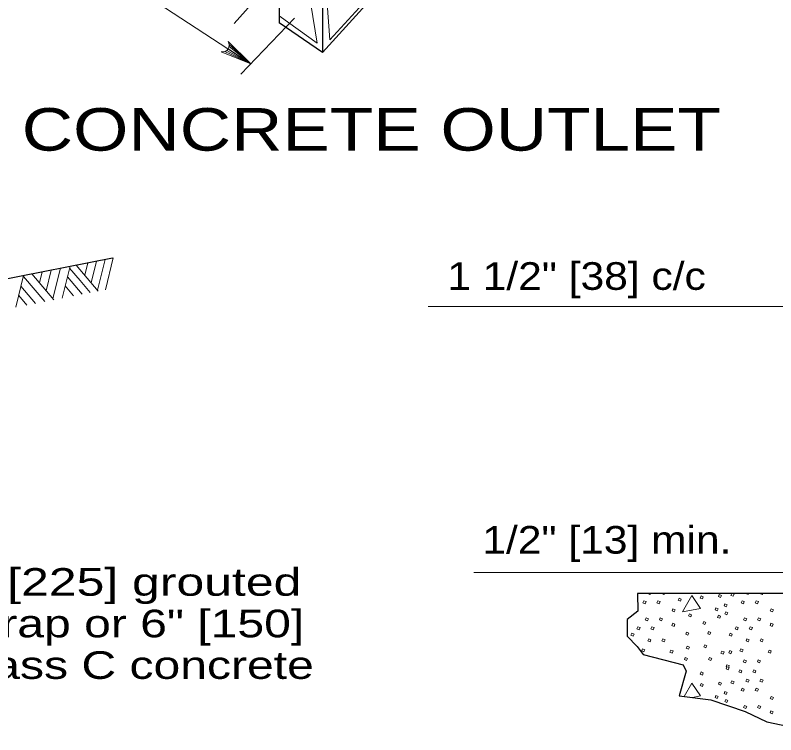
# Model space of a CAD drawing. Extents: x 1083.1 to 1117.1, y 697.4 to 741.4.
# Drawn here: x 1097.384 to 1101.675, y 729.151 to 733.213 of the extents above; entities that cross this region are included whole.
import ezdxf

# ---------------------------------------------------------------- set-up
doc = ezdxf.new("R2010")
doc.units = 0
doc.header["$LTSCALE"] = 0.062
doc.layers.add('1', color=7, linetype='Continuous', lineweight=13)

msp = doc.modelspace()

# ---------------------------------------------------------------- linework, layer by layer
at = {"layer": '1'}
for p, q in [((1098.61942, 733.16592), (1099.34742, 733.98267)), ((1098.71317, 732.93875), (1097.63775, 733.64192)), ((1098.96042, 733.19633), (1098.65742, 732.88083)), ((1098.591, 733.04817), (1098.71317, 732.93875)), ((1098.56675, 733.00767), (1098.71317, 732.93875)), ((1098.57733, 733.01392), (1098.71317, 732.93875)), ((1098.58492, 733.0225), (1098.71317, 732.93875)), ((1098.5905, 733.03617), (1098.71317, 732.93875)), ((1097.93658, 731.84333), (1097.8925, 731.66317)), ((1097.72817, 731.80233), (1097.85183, 731.65558)), ((1097.794, 731.81525), (1097.77708, 731.7445)), ((1097.84192, 731.82475), (1097.81267, 731.70267)), ((1097.8915, 731.8345), (1097.84883, 731.66042)), ((1097.53617, 731.7645), (1097.52108, 731.70267)), ((1097.58742, 731.77458), (1097.55858, 731.65792)), ((1097.63925, 731.78475), (1097.5965, 731.61333)), ((1097.69325, 731.7955), (1097.649, 731.61575)), ((1097.69067, 731.78433), (1097.74933, 731.71517)), ((1097.43083, 731.74383), (1097.3865, 731.564)), ((1097.42975, 731.73883), (1097.54983, 731.59625)), ((1097.47808, 731.75308), (1097.60225, 731.6065)), ((1097.67867, 731.73633), (1097.76225, 731.638)), ((1097.74933, 731.71517), (1097.80675, 731.64683)), ((1097.41608, 731.68308), (1097.4975, 731.58592)), ((1097.666, 731.68442), (1097.71267, 731.62825)), ((1097.404, 731.63067), (1097.44908, 731.57633)), ((1102.63992, 731.56783), (1099.71408, 731.56783)), ((1099.97208, 730.06625), (1103.79292, 730.06625)), ((1101.39442, 729.53533), (1101.39942, 729.54675)), ((1101.20075, 729.44292), (1101.158, 729.36708))]:
    msp.add_line(p, q, dxfattribs=at)
at = {"layer": '1', "lineweight": 25}
for p, q in [((1099.11717, 733.00283), (1099.59808, 733.531)), ((1098.87317, 733.45058), (1098.87317, 733.16992)), ((1099.11717, 733.2835), (1099.11717, 733.00283)), ((1099.11717, 733.00283), (1098.87317, 733.16992)), ((1096.21767, 731.505), (1097.9335, 731.84267)), ((1100.89692, 729.84967), (1100.83692, 729.80233))]:
    msp.add_line(p, q, dxfattribs=at)
at = {"layer": '1'}
for points in [[(1098.87317, 733.3975), (1098.87492, 733.39883), (1099.05217, 733.275), (1099.08667, 733.05583), (1098.87317, 733.2095)], [(1098.58442, 733.06525), (1098.71317, 732.93875), (1098.54567, 733.00592)], [(1100.96775, 729.94858), (1100.96508, 729.9425), (1100.95258, 729.94792), (1100.95292, 729.94858)], [(1101.04692, 729.94858), (1101.04433, 729.9425), (1101.03183, 729.94792), (1101.03208, 729.94858)], [(1101.42992, 729.94858), (1101.43958, 729.94442), (1101.43442, 729.93258), (1101.42192, 729.938), (1101.42658, 729.94858)], [(1101.52208, 729.94858), (1101.51942, 729.9425), (1101.50692, 729.94792), (1101.50725, 729.94858)], [(1101.60125, 729.94858), (1101.59858, 729.9425), (1101.58608, 729.94792), (1101.58642, 729.94858)], [(1101.39942, 729.54675), (1101.41192, 729.54133), (1101.40933, 729.53533)], [(1101.20508, 729.36133), (1101.25075, 729.37025), (1101.20075, 729.44292)]]:
    msp.add_lwpolyline(points, dxfattribs=at)
for points in [[(1099.15817, 733.07442), (1099.14325, 733.2795), (1099.26625, 733.41375), (1099.40783, 733.34658)], [(1101.12942, 729.92267), (1101.14192, 729.91725), (1101.13675, 729.90542), (1101.12425, 729.91083)], [(1101.20075, 729.93733), (1101.1485, 729.84475), (1101.25075, 729.86475)], [(1101.25358, 729.93492), (1101.26608, 729.9295), (1101.26092, 729.91767), (1101.24842, 729.92308)], [(1101.35633, 729.94275), (1101.36883, 729.93733), (1101.36367, 729.9255), (1101.35117, 729.93092)], [(1100.93083, 729.908), (1100.94333, 729.90258), (1100.93817, 729.89083), (1100.92567, 729.89625)], [(1101.01008, 729.908), (1101.02258, 729.90258), (1101.01742, 729.89083), (1101.00492, 729.89625)], [(1101.38817, 729.89042), (1101.40058, 729.885), (1101.3955, 729.87317), (1101.383, 729.87858)], [(1101.48517, 729.908), (1101.49767, 729.90258), (1101.4925, 729.89083), (1101.48, 729.89625)], [(1101.56442, 729.908), (1101.57683, 729.90258), (1101.57175, 729.89083), (1101.55925, 729.89625)], [(1101.095, 729.86208), (1101.1075, 729.85667), (1101.10233, 729.84483), (1101.08983, 729.85025)], [(1101.18775, 729.83417), (1101.20025, 729.82875), (1101.19508, 729.81692), (1101.18258, 729.82233)], [(1101.33783, 729.86775), (1101.35033, 729.86233), (1101.34517, 729.8505), (1101.33267, 729.85592)], [(1101.39242, 729.84483), (1101.40483, 729.83942), (1101.39975, 729.82758), (1101.38725, 729.833)], [(1101.64933, 729.86208), (1101.66183, 729.85667), (1101.65667, 729.84483), (1101.64417, 729.85025)], [(1100.94425, 729.81083), (1100.95675, 729.80542), (1100.95158, 729.79358), (1100.93908, 729.799)], [(1101.0235, 729.81083), (1101.036, 729.80542), (1101.03083, 729.79358), (1101.01833, 729.799)], [(1101.26842, 729.791), (1101.28092, 729.78558), (1101.27575, 729.77375), (1101.26325, 729.77917)], [(1101.35133, 729.82567), (1101.36383, 729.82025), (1101.35867, 729.80842), (1101.34617, 729.81383)], [(1101.49858, 729.81083), (1101.51108, 729.80542), (1101.50592, 729.79358), (1101.49342, 729.799)], [(1101.57775, 729.81083), (1101.59025, 729.80542), (1101.58508, 729.79358), (1101.57258, 729.799)], [(1100.89683, 729.76125), (1100.90933, 729.75583), (1100.90417, 729.74408), (1100.89167, 729.7495)], [(1100.97608, 729.76125), (1100.98858, 729.75583), (1100.98342, 729.74408), (1100.97092, 729.7495)], [(1101.09358, 729.78033), (1101.10608, 729.77492), (1101.10092, 729.76308), (1101.08842, 729.7685)], [(1101.45117, 729.76125), (1101.46367, 729.75583), (1101.4585, 729.74408), (1101.446, 729.7495)], [(1101.53042, 729.76125), (1101.54292, 729.75583), (1101.53775, 729.74408), (1101.52525, 729.7495)], [(1101.64792, 729.78033), (1101.66042, 729.77492), (1101.65525, 729.76308), (1101.64275, 729.7685)], [(1100.86292, 729.72517), (1100.87533, 729.71975), (1100.87017, 729.70792), (1100.85775, 729.71333)], [(1101.17217, 729.73017), (1101.18467, 729.72475), (1101.1795, 729.71292), (1101.167, 729.71833)], [(1101.29608, 729.73367), (1101.30858, 729.72825), (1101.30342, 729.71642), (1101.29092, 729.72183)], [(1101.41717, 729.72517), (1101.42967, 729.71975), (1101.4245, 729.70792), (1101.412, 729.71333)], [(1100.95842, 729.69258), (1100.97092, 729.68717), (1100.96575, 729.67533), (1100.95325, 729.68075)], [(1101.03767, 729.69258), (1101.05008, 729.68717), (1101.04492, 729.67533), (1101.0325, 729.68075)], [(1101.27408, 729.65933), (1101.28658, 729.65392), (1101.28142, 729.64208), (1101.26892, 729.6475)], [(1101.51275, 729.69258), (1101.52525, 729.68717), (1101.52008, 729.67533), (1101.50758, 729.68075)], [(1101.59192, 729.69258), (1101.60442, 729.68717), (1101.59925, 729.67533), (1101.58675, 729.68075)], [(1100.92375, 729.63667), (1100.93625, 729.63125), (1100.93108, 729.61942), (1100.91858, 729.62483)], [(1101.08292, 729.62958), (1101.09542, 729.62417), (1101.09025, 729.61242), (1101.07775, 729.61775)], [(1101.17508, 729.651), (1101.18758, 729.64558), (1101.18242, 729.63375), (1101.16992, 729.63917)], [(1101.3705, 729.62392), (1101.383, 729.6185), (1101.37783, 729.60675), (1101.36533, 729.61208)], [(1101.415, 729.626), (1101.4275, 729.62058), (1101.42233, 729.60883), (1101.40983, 729.61417)], [(1101.47808, 729.63667), (1101.49058, 729.63125), (1101.48542, 729.61942), (1101.47292, 729.62483)], [(1101.63725, 729.62958), (1101.64975, 729.62417), (1101.64458, 729.61242), (1101.63208, 729.61775)], [(1101.16467, 729.58692), (1101.17717, 729.5815), (1101.172, 729.56967), (1101.1595, 729.57508)], [(1101.301, 729.58717), (1101.3135, 729.58175), (1101.30833, 729.56992), (1101.29583, 729.57533)], [(1101.49717, 729.57442), (1101.50967, 729.569), (1101.5045, 729.55717), (1101.492, 729.56258)], [(1101.57633, 729.57442), (1101.58883, 729.569), (1101.58367, 729.55717), (1101.57117, 729.56258)], [(1101.39942, 729.53533), (1101.41192, 729.52992), (1101.40675, 729.51808), (1101.39433, 729.5235)], [(1101.25358, 729.50558), (1101.26608, 729.50017), (1101.26092, 729.48833), (1101.24842, 729.49375)], [(1101.47167, 729.51833), (1101.48417, 729.51292), (1101.479, 729.50108), (1101.4665, 729.5065)], [(1101.55092, 729.51833), (1101.56342, 729.51292), (1101.55825, 729.50108), (1101.54575, 729.5065)], [(1101.25358, 729.4405), (1101.26608, 729.43508), (1101.26092, 729.42325), (1101.24842, 729.42867)], [(1101.35633, 729.44833), (1101.36883, 729.44292), (1101.36367, 729.43108), (1101.35117, 729.4365)], [(1101.42708, 729.45542), (1101.43958, 729.45), (1101.43442, 729.43817), (1101.42192, 729.44358)], [(1101.51208, 729.46533), (1101.52458, 729.45992), (1101.51942, 729.44808), (1101.50692, 729.4535)], [(1101.59125, 729.46533), (1101.60375, 729.45992), (1101.59858, 729.44808), (1101.58608, 729.4535)], [(1101.48517, 729.41358), (1101.49767, 729.40817), (1101.4925, 729.39633), (1101.48, 729.40175)], [(1101.56442, 729.41358), (1101.57683, 729.40817), (1101.57175, 729.39633), (1101.55925, 729.40175)], [(1101.33783, 729.37325), (1101.35033, 729.36783), (1101.34517, 729.356), (1101.33267, 729.36142)], [(1101.38817, 729.39592), (1101.40058, 729.3905), (1101.3955, 729.37867), (1101.383, 729.38408)], [(1101.64933, 729.36758), (1101.66183, 729.36217), (1101.65667, 729.35033), (1101.64417, 729.35575)], [(1101.39242, 729.35033), (1101.40483, 729.34492), (1101.39975, 729.33308), (1101.38725, 729.3385)], [(1101.49858, 729.31642), (1101.51108, 729.311), (1101.50592, 729.29917), (1101.49342, 729.30458)], [(1101.57775, 729.31642), (1101.59025, 729.311), (1101.58508, 729.29917), (1101.57258, 729.30458)], [(1101.64792, 729.28592), (1101.66042, 729.2805), (1101.65525, 729.26867), (1101.64275, 729.27408)]]:
    msp.add_lwpolyline(points, close=True, dxfattribs=at)
at = {"layer": '1', "lineweight": 25}
for points in [[(1106.36717, 729.94858), (1100.89558, 729.94858), (1100.89692, 729.84967)], [(1100.83692, 729.80233), (1100.83692, 729.70742), (1100.89383, 729.64883), (1100.92625, 729.60483), (1101.1535, 729.54625), (1101.17, 729.50958), (1101.12925, 729.37058), (1101.308, 729.34875), (1101.50292, 729.28267), (1101.62458, 729.22408), (1101.97392, 729.151)]]:
    msp.add_lwpolyline(points, dxfattribs=at)
at = {"layer": '1'}
msp.add_arc((1098.55302, 733.04337), 0.0382, 258.90799, 34.73412, dxfattribs=at)

# ---------------------------------------------------------------- texts
for s, height, width, p in [('PRECAST REINFORCED CONCRETE OUTLET', 0.24, 1.25, (1092.6505, 732.44833)), ('1 1/2" [38] c/c', 0.156, 1.15, (1099.8215, 731.66258)), ('1/2" [13] min.', 0.156, 1.15, (1100.01958, 730.17367)), ('9" [225] grouted', 0.156, 1.35, (1097.00375, 729.93583)), ('riprap or 6" [150]', 0.156, 1.3, (1097.00375, 729.70117)), ('Class C concrete', 0.156, 1.3, (1097.00375, 729.4665))]:
    msp.add_text(s, height=height, dxfattribs=dict(at, width=width)).set_placement(p)

doc.saveas('drawing.dxf')
